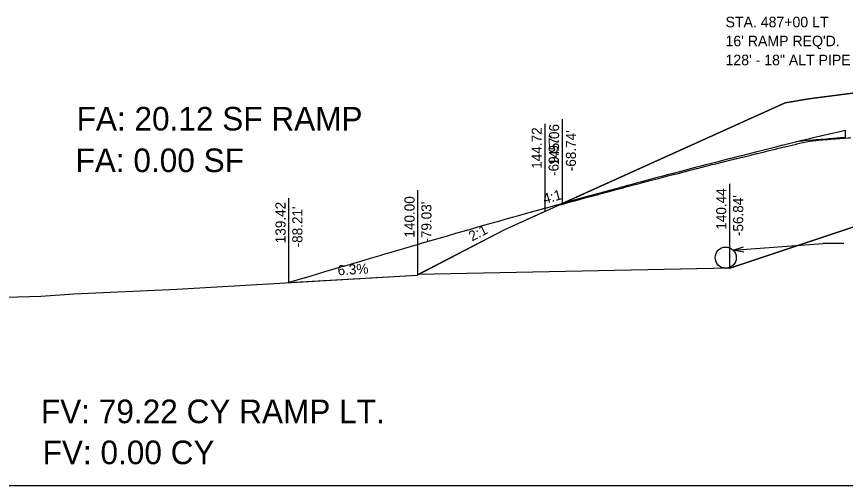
# Model space of a CAD drawing. Extents: x -100 to 4303, y -13 to 10775.
# Drawn here: x 3042.4 to 3101.4, y 5500 to 5533.4 of the extents above; entities that cross this region are included whole.
import ezdxf

# ---------------------------------------------------------------- set-up
doc = ezdxf.new("R2010")
doc.units = 0
for name, color, linetype in [('CONST_DCH', 7, 'Continuous'), ('DTM_CONTOURS_MINOR', 7, 'Continuous'), ('DTM_P_FINISHED_GRADE', 7, 'Continuous'), ('DTM_X_GROUND', 7, 'Continuous'), ('X_PROFILES_1', 7, 'Continuous'), ('XS_CELL', 7, 'Continuous'), ('XS_M_SHAPES_EARTHWORK', 7, 'Continuous'), ('XS_P_DR_GRAVEL', 7, 'Continuous'), ('XS_P_DRAINAGE', 7, 'Continuous'), ('XS_P_GROUND', 7, 'Continuous'), ('XS_P_TX_CLEARZONE', 7, 'Continuous'), ('XS_P_TX_FS_BS', 7, 'Continuous'), ('XS_SHEET_EW_TX_AREA', 7, 'Continuous'), ('XS_SHEET_EW_TX_VOLUME', 7, 'Continuous'), ('XS_X_EXCESS', 7, 'Continuous')]:
    doc.layers.add(name, color=color, linetype=linetype)

msp = doc.modelspace()

# ---------------------------------------------------------------- linework, layer by layer
at = {"layer": 'DTM_P_FINISHED_GRADE'}
msp.add_lwpolyline([(3098.868, 5524.501), (3099.286, 5524.536), (3099.509, 5524.555), (3100.037, 5524.599), (3100.124, 5524.607), (3100.607, 5524.647), (3100.649, 5524.651), (3101.598, 5524.73)], dxfattribs=at)
at = {"layer": 'DTM_X_GROUND'}
msp.add_lwpolyline([(3000, 5512.2), (3044.132, 5513.453), (3046.486, 5513.62), (3053.808, 5513.95), (3070.909, 5514.966), (3077.153, 5518.209), (3097.118, 5527.209), (3098.789, 5527.5), (3101.713, 5527.882), (3110.312, 5528.066), (3113.777, 5528.123), (3116.864, 5528.039), (3124.572, 5527.826)], dxfattribs=at)
at = {"layer": 'XS_CELL'}
msp.add_line((3000, 5500), (3150, 5500), dxfattribs=at)
msp.add_line((3000, 5500), (3150, 5500), dxfattribs=at)
at = {"layer": 'XS_M_SHAPES_EARTHWORK'}
for points in [[(3070.973, 5514.999), (3077.153, 5518.209), (3097.118, 5527.209), (3098.789, 5527.5), (3101.713, 5527.882), (3110.312, 5528.066), (3113.777, 5528.123), (3116.864, 5528.039), (3124.572, 5527.826), (3125.877, 5527.605), (3129.562, 5526.928), (3131.005, 5526.033), (3126.052, 5525.901), (3120, 5524.389), (3093.161, 5515.443)], [(3061.789, 5514.424), (3070.909, 5514.966), (3077.153, 5518.209), (3080.029, 5519.505), (3080.029, 5519.721), (3079.738, 5519.637), (3079.281, 5519.504), (3078.61, 5519.321), (3078.045, 5519.165), (3077.701, 5519.065), (3077.671, 5519.056), (3077.653, 5519.051), (3077.086, 5518.894), (3076.776, 5518.802), (3075.9, 5518.557), (3075.477, 5518.433), (3075.055, 5518.314), (3074.872, 5518.26), (3073.655, 5517.915), (3073.202, 5517.78), (3072.971, 5517.714), (3072.894, 5517.691), (3071.277, 5517.228), (3070.834, 5517.094), (3070.823, 5517.091), (3070.82, 5517.09), (3069.034, 5516.573), (3068.688, 5516.468), (3068.375, 5516.376), (3068.322, 5516.36), (3067.676, 5516.172), (3067.58, 5516.142), (3066.566, 5515.845), (3066.448, 5515.809), (3065.76, 5515.606), (3065.695, 5515.586), (3064.189, 5515.141), (3064.106, 5515.115), (3062.957, 5514.773), (3062.927, 5514.764)]]:
    msp.add_lwpolyline(points, close=True, dxfattribs=at)
at = {"layer": 'XS_P_DR_GRAVEL'}
for points in [[(3101.435, 5524.75), (3101.397, 5524.747), (3101.397, 5525.247), (3101.435, 5525.25)], [(3101.435, 5524.75), (3101.397, 5524.747), (3101.397, 5525.247), (3101.435, 5525.25)], [(3101.397, 5524.747), (3101.103, 5524.723), (3101.014, 5524.715), (3100.265, 5524.653), (3100.065, 5524.637), (3099.734, 5524.609), (3099.703, 5524.607), (3099.67, 5524.604), (3099.31, 5524.574), (3099.069, 5524.554), (3098.428, 5524.502), (3098.331, 5524.494), (3098.004, 5524.467)], [(3101.397, 5524.747), (3101.103, 5524.723), (3101.014, 5524.715), (3100.265, 5524.653), (3100.065, 5524.637), (3099.734, 5524.609), (3099.703, 5524.607), (3099.67, 5524.604), (3099.31, 5524.574), (3099.069, 5524.554), (3098.428, 5524.502), (3098.331, 5524.494), (3098.004, 5524.467)]]:
    msp.add_lwpolyline(points, dxfattribs=at)
at = {"layer": 'XS_P_DRAINAGE'}
for p in [(3093.407, 5516.735), (3101.291, 5517.206)]:
    msp.add_line(p, (3099.791, 5517.206), dxfattribs=at)
msp.add_lwpolyline([(3094.169, 5516.603), (3093.407, 5516.735), (3094.141, 5516.977)], dxfattribs=at)
msp.add_circle((3092.877, 5516.205), 0.75, dxfattribs=at)
at = {"layer": 'XS_P_GROUND'}
for points in [[(3093.161, 5515.443), (3120, 5524.389), (3120, 5524.389), (3120, 5524.389), (3132, 5527.389)], [(3101.397, 5525.247), (3101.103, 5525.183), (3101.097, 5525.181), (3100.265, 5524.998), (3100.25, 5524.993), (3099.734, 5524.877), (3099.731, 5524.876), (3099.67, 5524.863), (3099.644, 5524.854), (3099.069, 5524.723), (3099.025, 5524.708), (3098.331, 5524.547), (3098.292, 5524.534), (3097.846, 5524.429), (3097.757, 5524.399), (3096.89, 5524.19), (3096.855, 5524.179), (3096.596, 5524.115), (3096.441, 5524.064), (3095.41, 5523.806), (3095.395, 5523.801), (3095.315, 5523.781), (3095.096, 5523.729), (3094.003, 5523.451), (3093.98, 5523.446), (3093.888, 5523.422), (3093.775, 5523.396), (3093.334, 5523.282), (3093.186, 5523.246), (3092.657, 5523.109), (3092.577, 5523.09), (3092.32, 5523.023), (3092.059, 5522.959), (3091.275, 5522.753), (3091.117, 5522.714), (3090.703, 5522.605), (3090.453, 5522.543), (3089.855, 5522.383), (3089.594, 5522.318), (3089.033, 5522.167), (3088.816, 5522.113), (3088.394, 5521.998), (3088.001, 5521.898), (3087.306, 5521.709), (3087.146, 5521.668), (3086.89, 5521.598), (3086.582, 5521.518), (3086.121, 5521.391), (3085.868, 5521.325), (3085.519, 5521.228), (3085.441, 5521.208), (3085.34, 5521.18), (3084.616, 5520.99), (3083.741, 5520.745), (3083.704, 5520.735), (3083.665, 5520.724), (3082.751, 5520.478), (3082.088, 5520.291), (3081.862, 5520.229), (3081.74, 5520.194), (3080.034, 5519.706)], [(3101.397, 5525.247), (3101.103, 5525.183), (3101.097, 5525.181), (3100.265, 5524.998), (3100.25, 5524.993), (3099.734, 5524.877), (3099.731, 5524.876), (3099.67, 5524.863), (3099.644, 5524.854), (3099.069, 5524.723), (3099.025, 5524.708), (3098.331, 5524.547), (3098.292, 5524.534), (3097.846, 5524.429), (3097.757, 5524.399), (3096.89, 5524.19), (3096.855, 5524.179), (3096.596, 5524.115), (3096.441, 5524.064), (3095.41, 5523.806), (3095.395, 5523.801), (3095.315, 5523.781), (3095.096, 5523.729), (3094.003, 5523.451), (3093.98, 5523.446), (3093.888, 5523.422), (3093.775, 5523.396), (3093.334, 5523.282), (3093.186, 5523.246), (3092.657, 5523.109), (3092.577, 5523.09), (3092.32, 5523.023), (3092.059, 5522.959), (3091.275, 5522.753), (3091.117, 5522.714), (3090.703, 5522.605), (3090.453, 5522.543), (3089.855, 5522.383), (3089.594, 5522.318), (3089.033, 5522.167), (3088.816, 5522.113), (3088.394, 5521.998), (3088.001, 5521.898), (3087.306, 5521.709), (3087.146, 5521.668), (3086.89, 5521.598), (3086.582, 5521.518), (3086.121, 5521.391), (3085.868, 5521.325), (3085.519, 5521.228), (3085.441, 5521.208), (3085.34, 5521.18), (3084.616, 5520.99), (3083.741, 5520.745), (3083.704, 5520.735), (3083.665, 5520.724), (3082.751, 5520.478), (3082.088, 5520.291), (3081.862, 5520.229), (3081.74, 5520.194), (3080.034, 5519.706)], [(3101.397, 5525.247), (3101.103, 5525.183), (3101.097, 5525.181), (3100.265, 5524.998), (3100.25, 5524.993), (3099.734, 5524.877), (3099.731, 5524.876), (3099.67, 5524.863), (3099.644, 5524.854), (3099.069, 5524.723), (3099.025, 5524.708), (3098.331, 5524.547), (3098.292, 5524.534), (3097.846, 5524.429), (3097.757, 5524.399), (3096.89, 5524.19), (3096.855, 5524.179), (3096.596, 5524.115), (3096.441, 5524.064), (3095.41, 5523.806), (3095.395, 5523.801), (3095.315, 5523.781), (3095.096, 5523.729), (3094.003, 5523.451), (3093.98, 5523.446), (3093.888, 5523.422), (3093.775, 5523.396), (3093.334, 5523.282), (3093.186, 5523.246), (3092.657, 5523.109), (3092.577, 5523.09), (3092.32, 5523.023), (3092.059, 5522.959), (3091.275, 5522.753), (3091.117, 5522.714), (3090.703, 5522.605), (3090.453, 5522.543), (3089.855, 5522.383), (3089.594, 5522.318), (3089.033, 5522.167), (3088.816, 5522.113), (3088.394, 5521.998), (3088.001, 5521.898), (3087.306, 5521.709), (3087.146, 5521.668), (3086.89, 5521.598), (3086.582, 5521.518), (3086.121, 5521.391), (3085.868, 5521.325), (3085.519, 5521.228), (3085.441, 5521.208), (3085.34, 5521.18), (3084.616, 5520.99), (3083.741, 5520.745), (3083.704, 5520.735), (3083.665, 5520.724), (3082.751, 5520.478), (3082.088, 5520.291), (3081.862, 5520.229), (3081.74, 5520.194), (3081.259, 5520.057)], [(3101.397, 5525.247), (3101.103, 5525.183), (3101.097, 5525.181), (3100.265, 5524.998), (3100.25, 5524.993), (3099.734, 5524.877), (3099.731, 5524.876), (3099.67, 5524.863), (3099.644, 5524.854), (3099.069, 5524.723), (3099.025, 5524.708), (3098.331, 5524.547), (3098.292, 5524.534), (3097.846, 5524.429), (3097.757, 5524.399), (3096.89, 5524.19), (3096.855, 5524.179), (3096.596, 5524.115), (3096.441, 5524.064), (3095.41, 5523.806), (3095.395, 5523.801), (3095.315, 5523.781), (3095.096, 5523.729), (3094.003, 5523.451), (3093.98, 5523.446), (3093.888, 5523.422), (3093.775, 5523.396), (3093.334, 5523.282), (3093.186, 5523.246), (3092.657, 5523.109), (3092.577, 5523.09), (3092.32, 5523.023), (3092.059, 5522.959), (3091.275, 5522.753), (3091.117, 5522.714), (3090.703, 5522.605), (3090.453, 5522.543), (3089.855, 5522.383), (3089.594, 5522.318), (3089.033, 5522.167), (3088.816, 5522.113), (3088.394, 5521.998), (3088.001, 5521.898), (3087.306, 5521.709), (3087.146, 5521.668), (3086.89, 5521.598), (3086.582, 5521.518), (3086.121, 5521.391), (3085.868, 5521.325), (3085.519, 5521.228), (3085.441, 5521.208), (3085.34, 5521.18), (3084.616, 5520.99), (3083.741, 5520.745), (3083.704, 5520.735), (3083.665, 5520.724), (3082.751, 5520.478), (3082.088, 5520.291), (3081.862, 5520.229), (3081.74, 5520.194), (3081.259, 5520.057)], [(3080.029, 5519.721), (3079.738, 5519.637), (3079.281, 5519.504), (3078.61, 5519.321), (3078.045, 5519.165), (3077.701, 5519.065), (3077.671, 5519.056), (3077.653, 5519.051), (3077.086, 5518.894), (3076.776, 5518.802), (3075.9, 5518.557), (3075.477, 5518.433), (3075.055, 5518.314), (3074.872, 5518.26), (3073.655, 5517.915), (3073.202, 5517.78), (3072.971, 5517.714), (3072.894, 5517.691), (3071.277, 5517.228), (3070.834, 5517.094), (3070.823, 5517.091), (3070.82, 5517.09), (3069.034, 5516.573), (3068.688, 5516.468), (3068.375, 5516.376), (3068.322, 5516.36), (3067.676, 5516.172), (3067.58, 5516.142), (3066.566, 5515.845), (3066.448, 5515.809), (3065.76, 5515.606), (3065.695, 5515.586), (3064.189, 5515.141), (3064.106, 5515.115), (3062.957, 5514.773), (3062.927, 5514.764), (3061.789, 5514.424)], [(3080.029, 5519.721), (3079.738, 5519.637), (3079.281, 5519.504), (3078.61, 5519.321), (3078.045, 5519.165), (3077.701, 5519.065), (3077.671, 5519.056), (3077.653, 5519.051), (3077.086, 5518.894), (3076.776, 5518.802), (3075.9, 5518.557), (3075.477, 5518.433), (3075.055, 5518.314), (3074.872, 5518.26), (3073.655, 5517.915), (3073.202, 5517.78), (3072.971, 5517.714), (3072.894, 5517.691), (3071.277, 5517.228), (3070.834, 5517.094), (3070.823, 5517.091), (3070.82, 5517.09), (3069.034, 5516.573), (3068.688, 5516.468), (3068.375, 5516.376), (3068.322, 5516.36), (3067.676, 5516.172), (3067.58, 5516.142), (3066.566, 5515.845), (3066.448, 5515.809), (3065.76, 5515.606), (3065.695, 5515.586), (3064.189, 5515.141), (3064.106, 5515.115), (3062.957, 5514.773), (3062.927, 5514.764), (3061.789, 5514.424)], [(3093.161, 5515.443), (3070.973, 5514.999)]]:
    msp.add_lwpolyline(points, dxfattribs=at)
at = {"layer": 'XS_P_TX_CLEARZONE'}
for p, q in [((3081.259, 5520.057), (3081.259, 5526.057)), ((3081.259, 5520.057), (3081.259, 5526.057)), ((3080.029, 5519.721), (3080.029, 5525.721)), ((3080.029, 5519.721), (3080.029, 5525.721)), ((3093.161, 5515.443), (3093.161, 5521.443)), ((3093.161, 5515.443), (3093.161, 5521.443)), ((3070.973, 5514.999), (3070.973, 5520.999)), ((3070.973, 5514.999), (3070.973, 5520.999)), ((3061.789, 5514.424), (3061.789, 5520.424)), ((3061.789, 5514.424), (3061.789, 5520.424))]:
    msp.add_line(p, q, dxfattribs=at)
at = {"layer": 'XS_X_EXCESS'}
for p, q in [((3100.124, 5524.607), (3100.607, 5524.647)), ((3098.868, 5524.501), (3099.286, 5524.536)), ((3099.286, 5524.536), (3099.509, 5524.555)), ((3080.966, 5519.928), (3081.279, 5520.011))]:
    msp.add_line(p, q, dxfattribs=at)
for points in [[(3129.815, 5526.77), (3129.562, 5526.928), (3125.877, 5527.605), (3124.572, 5527.826), (3116.864, 5528.039), (3113.777, 5528.123), (3110.312, 5528.066), (3101.713, 5527.882), (3098.789, 5527.5), (3097.118, 5527.209), (3080.966, 5519.928)], [(3100.607, 5524.647), (3100.649, 5524.651), (3100.714, 5524.657), (3101.598, 5524.731), (3101.69, 5524.738), (3101.788, 5524.748)], [(3081.279, 5520.011), (3082.066, 5520.233), (3082.097, 5520.241), (3082.127, 5520.249), (3082.952, 5520.478), (3083.639, 5520.658), (3083.813, 5520.707), (3083.945, 5520.741), (3084.672, 5520.94), (3085.164, 5521.067), (3085.496, 5521.157), (3085.7, 5521.209), (3086.308, 5521.374), (3086.645, 5521.459), (3087.128, 5521.589), (3087.369, 5521.649), (3087.396, 5521.656), (3087.869, 5521.783), (3088.083, 5521.836), (3088.765, 5522.016), (3089.037, 5522.083), (3089.363, 5522.169), (3089.483, 5522.198), (3090.354, 5522.425), (3090.628, 5522.491), (3090.796, 5522.535), (3090.845, 5522.547), (3091.914, 5522.82), (3092.171, 5522.882), (3093.266, 5523.158), (3093.468, 5523.205), (3093.641, 5523.248), (3093.671, 5523.255), (3094.046, 5523.349), (3094.104, 5523.362), (3094.659, 5523.499), (3094.732, 5523.516), (3095.088, 5523.603), (3095.129, 5523.613), (3095.632, 5523.735), (3095.9, 5523.8), (3095.968, 5523.816), (3096.512, 5523.947), (3096.549, 5523.959), (3097.147, 5524.101), (3097.176, 5524.111), (3097.915, 5524.283), (3097.934, 5524.289), (3098.359, 5524.387), (3098.868, 5524.501)], [(3099.509, 5524.555), (3100.037, 5524.599), (3100.124, 5524.607)]]:
    msp.add_lwpolyline(points, dxfattribs=at)

# ---------------------------------------------------------------- texts
at = {"layer": 'CONST_DCH'}
for height, p in [(0.001, (3092.833, 5515.44)), (0.12, (3092.837, 5515.395))]:
    msp.add_text('X', height=height, dxfattribs=at).set_placement(p)
at = {"layer": 'DTM_CONTOURS_MINOR'}
msp.add_text('X', height=0.12, dxfattribs=at).set_placement((3070.934, 5514.939))
at = {"layer": 'X_PROFILES_1'}
for p in [(3081.22, 5519.997), (3081.22, 5519.997), (3079.99, 5519.661), (3079.99, 5519.661), (3093.121, 5515.383), (3061.75, 5514.364)]:
    msp.add_text('X', height=0.12, dxfattribs=at).set_placement(p)
at = {"layer": 'XS_P_DRAINAGE'}
for s, p in [('STA. 487+00 LT', (3092.864, 5532.591)), ("16' RAMP REQ'D.", (3092.864, 5531.241)), ('128\' - 18" ALT PIPE REQ\'D.', (3092.864, 5529.891))]:
    msp.add_text(s, height=0.75, dxfattribs=at).set_placement(p)
at = {"layer": 'XS_P_TX_CLEARZONE'}
for s, p in [('144.72', (3079.789, 5522.525)), ('144.72', (3079.789, 5522.525)), ('145.06', (3081.019, 5522.765)), ('145.06', (3081.019, 5522.765)), ("-68.74'", (3082.219, 5522.351)), ("-68.74'", (3082.219, 5522.351)), ("-69.97'", (3080.989, 5522.015)), ("-69.97'", (3080.989, 5522.015)), ('140.44', (3092.921, 5518.191)), ('140.44', (3092.921, 5518.191)), ('140.00', (3070.733, 5517.628)), ('140.00', (3070.733, 5517.628)), ("-56.84'", (3094.121, 5517.737)), ("-56.84'", (3094.121, 5517.737)), ('139.42', (3061.549, 5517.228)), ('139.42', (3061.549, 5517.228)), ("-79.03'", (3071.933, 5517.271)), ("-79.03'", (3071.933, 5517.271)), ("-88.21'", (3062.749, 5516.933)), ("-88.21'", (3062.749, 5516.933))]:
    msp.add_text(s, height=0.72, rotation=90, dxfattribs=at).set_placement(p)
at = {"layer": 'XS_P_TX_FS_BS'}
for s, rotation, p in [('4:1', 15.2624, (3079.975, 5520.017)), ('4:1', 15.2624, (3079.975, 5520.017)), ('2:1', 27.53712, (3074.82, 5517.343)), ('6.3%', 3.58525, (3065.274, 5514.943))]:
    msp.add_text(s, height=0.72, rotation=rotation, dxfattribs=at).set_placement(p)
at = {"layer": 'XS_SHEET_EW_TX_AREA'}
for s, p in [('FA: 20.12 SF RAMP', (3046.678, 5525.248)), ('FA: 0.00 SF', (3046.601, 5522.287))]:
    msp.add_text(s, height=1.68, dxfattribs=at).set_placement(p)
at = {"layer": 'XS_SHEET_EW_TX_VOLUME'}
for s, p in [('FV: 79.22 CY RAMP LT.', (3044.138, 5504.426)), ('FV: 0.00 CY', (3044.258, 5501.511))]:
    msp.add_text(s, height=1.68, dxfattribs=at).set_placement(p)

doc.saveas('drawing.dxf')
